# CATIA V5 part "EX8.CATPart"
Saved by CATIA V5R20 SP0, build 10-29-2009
Part number: EX8
Bounding box of the stored display mesh (mm): x -31.327 to 43.169, y -66.279 to 0, z 0 to 10
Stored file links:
  E:\Nouveau dossier\tarek\mécaniquee\Catia\TP 0\EX8.CATPart
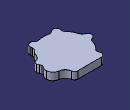
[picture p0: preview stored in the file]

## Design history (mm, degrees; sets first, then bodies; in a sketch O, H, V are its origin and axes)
Set1
  DatumSurface1 to DatumSurface29
Body1 (main body)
